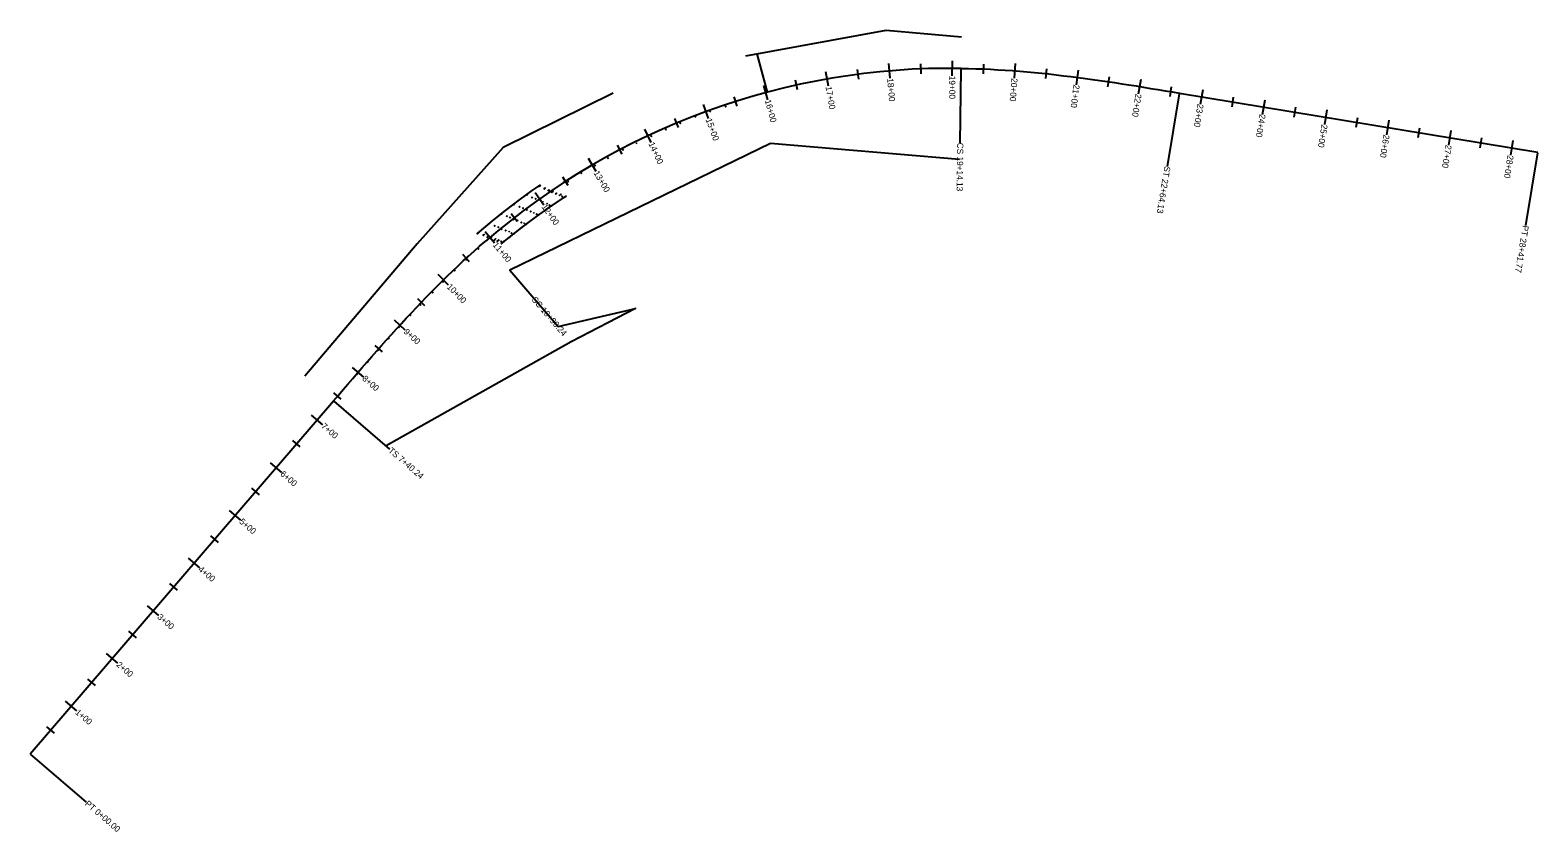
# Model space of a CAD drawing. Extents: x 153371 to 155769, y 329648 to 330923.
import ezdxf

# ---------------------------------------------------------------- set-up
doc = ezdxf.new("R2010")
doc.units = 0
for name, color, linetype in [('Default', 7, 'Continuous'), ('DT_X_Break_Line', 7, 'Continuous'), ('DT_X_Spot_Elev', 7, 'Continuous'), ('DT_X_Terrain_Ground_Line', 7, 'Continuous'), ('DT_X_Triangles', 7, 'Continuous'), ('DT_X_Void', 7, 'Continuous')]:
    doc.layers.add(name, color=color, linetype=linetype)

msp = doc.modelspace()

# ---------------------------------------------------------------- linework, layer by layer
at = {"layer": 'Default'}
for p, q in [((154526.9, 330885.3), (154543.2, 330824.1)), ((154640.7, 330833.5), (154636.6, 330856.7)), ((154640.7, 330833.5), (154636.6, 330856.7)), ((154689.1, 330844.8), (154687, 330860.4)), ((154689.1, 330844.8), (154687, 330860.4)), ((154738.8, 330846.2), (154736.8, 330869.7)), ((154738.8, 330846.2), (154736.8, 330869.7)), ((154788, 330853.2), (154787.3, 330869)), ((154788, 330853.2), (154787.3, 330869)), ((154837.6, 330850.2), (154837.7, 330873.9)), ((154837.6, 330850.2), (154837.7, 330873.9)), ((154850.3, 330743.8), (154851.8, 330860.9)), ((154850.3, 330743.8), (154851.8, 330860.9)), ((154887.3, 330853.2), (154887.9, 330868.9)), ((154887.3, 330853.2), (154887.9, 330868.9)), ((154936.6, 330846.3), (154938.4, 330869.9)), ((154936.6, 330846.3), (154938.4, 330869.9)), ((154986.5, 330845.7), (154988.2, 330861.4)), ((154986.5, 330845.7), (154988.2, 330861.4)), ((155035.4, 330835.9), (155038.5, 330859.3)), ((155035.4, 330835.9), (155038.5, 330859.3)), ((154544.1, 330812.1), (154538, 330834.9)), ((154544.1, 330812.1), (154538, 330834.9)), ((154591.3, 330827.7), (154587.9, 330843.1)), ((154591.3, 330827.7), (154587.9, 330843.1)), ((155085.3, 330832.9), (155087.7, 330848.5)), ((155085.3, 330832.9), (155087.7, 330848.5)), ((155134, 330821.4), (155137.8, 330844.7)), ((155134, 330821.4), (155137.8, 330844.7)), ((155184, 330817.2), (155186.5, 330832.7)), ((155184, 330817.2), (155186.5, 330832.7)), ((154495.4, 330802), (154490.6, 330817)), ((154495.4, 330802), (154490.6, 330817)), ((155179.9, 330706.1), (155199, 330821.7)), ((155179.9, 330706.1), (155199, 330821.7)), ((155232.7, 330805.2), (155236.5, 330828.5)), ((155232.7, 330805.2), (155236.5, 330828.5)), ((155282.6, 330800.9), (155285.2, 330816.5)), ((155282.6, 330800.9), (155285.2, 330816.5)), ((155331.3, 330788.9), (155335.2, 330812.2)), ((155331.3, 330788.9), (155335.2, 330812.2)), ((154402.2, 330767.9), (154396.1, 330782.4)), ((154402.2, 330767.9), (154396.1, 330782.4)), ((154449.8, 330782.3), (154441.6, 330804.5)), ((154449.8, 330782.3), (154441.6, 330804.5)), ((155381.3, 330784.6), (155383.9, 330800.2)), ((155381.3, 330784.6), (155383.9, 330800.2)), ((155430, 330772.6), (155433.8, 330795.9)), ((155430, 330772.6), (155433.8, 330795.9)), ((155480, 330768.4), (155482.5, 330783.9)), ((155480, 330768.4), (155482.5, 330783.9)), ((154358.4, 330744.2), (154348.4, 330765.6)), ((154358.4, 330744.2), (154348.4, 330765.6)), ((155528.7, 330756.4), (155532.5, 330779.7)), ((155528.7, 330756.4), (155532.5, 330779.7)), ((155578.6, 330752.1), (155581.2, 330767.6)), ((155578.6, 330752.1), (155581.2, 330767.6)), ((155627.3, 330740.1), (155631.2, 330763.4)), ((155627.3, 330740.1), (155631.2, 330763.4)), ((154312.3, 330725.7), (154305, 330739.7)), ((154312.3, 330725.7), (154305, 330739.7)), ((155677.3, 330735.8), (155679.9, 330751.4)), ((155677.3, 330735.8), (155679.9, 330751.4)), ((155726, 330723.8), (155729.8, 330747.1)), ((155726, 330723.8), (155729.8, 330747.1)), ((154270.8, 330698.3), (154259, 330718.7)), ((154270.8, 330698.3), (154259, 330718.7)), ((155749.9, 330612.1), (155769, 330727.7)), ((155749.9, 330612.1), (155769, 330727.7)), ((154226.5, 330675.7), (154218, 330689)), ((154226.5, 330675.7), (154218, 330689)), ((154187.6, 330644.8), (154174, 330664)), ((154187.6, 330644.8), (154174, 330664)), ((154145.5, 330618.4), (154135.8, 330630.8)), ((154145.5, 330618.4), (154135.8, 330630.8)), ((154109.5, 330584.1), (154094.2, 330602.1)), ((154109.5, 330584.1), (154094.2, 330602.1)), ((154069.6, 330554.3), (154059, 330565.9)), ((154069.6, 330554.3), (154059, 330565.9)), ((154036.3, 330517.3), (154019.7, 330534.1)), ((154036.3, 330517.3), (154019.7, 330534.1)), ((153998.5, 330484.7), (153987.2, 330495.6)), ((153998.5, 330484.7), (153987.2, 330495.6)), ((153967.4, 330445.7), (153950, 330461.6)), ((153967.4, 330445.7), (153950, 330461.6)), ((153931.1, 330411.3), (153919.3, 330421.7)), ((153931.1, 330411.3), (153919.3, 330421.7)), ((153901.2, 330371.1), (153883.4, 330386.6)), ((153901.2, 330371.1), (153883.4, 330386.6)), ((153865.6, 330335.9), (153853.7, 330346.1)), ((153865.6, 330335.9), (153853.7, 330346.1)), ((153942.9, 330256.6), (153854, 330333)), ((153942.9, 330256.6), (153854, 330333)), ((153836, 330295.4), (153818.1, 330310.8)), ((153836, 330295.4), (153818.1, 330310.8)), ((153800.4, 330260.1), (153788.5, 330270.3)), ((153800.4, 330260.1), (153788.5, 330270.3)), ((153770.8, 330219.6), (153752.9, 330235)), ((153770.8, 330219.6), (153752.9, 330235)), ((153735.2, 330184.2), (153723.3, 330194.5)), ((153735.2, 330184.2), (153723.3, 330194.5)), ((153705.6, 330143.8), (153687.7, 330159.2)), ((153705.6, 330143.8), (153687.7, 330159.2)), ((153670, 330108.4), (153658.1, 330118.7)), ((153670, 330108.4), (153658.1, 330118.7)), ((153640.4, 330067.9), (153622.5, 330083.4)), ((153640.4, 330067.9), (153622.5, 330083.4)), ((153604.8, 330032.6), (153592.8, 330042.9)), ((153604.8, 330032.6), (153592.8, 330042.9)), ((153575.2, 329992.1), (153557.3, 330007.5)), ((153575.2, 329992.1), (153557.3, 330007.5)), ((153539.6, 329956.8), (153527.6, 329967.1)), ((153539.6, 329956.8), (153527.6, 329967.1)), ((153510, 329916.3), (153492, 329931.7)), ((153510, 329916.3), (153492, 329931.7)), ((153474.4, 329881), (153462.4, 329891.2)), ((153474.4, 329881), (153462.4, 329891.2)), ((153444.8, 329840.5), (153426.8, 329855.9)), ((153444.8, 329840.5), (153426.8, 329855.9)), ((153409.2, 329805.2), (153397.2, 329815.4)), ((153409.2, 329805.2), (153397.2, 329815.4)), ((153460.1, 329695.4), (153371.3, 329771.7)), ((153460.1, 329695.4), (153371.3, 329771.7))]:
    msp.add_line(p, q, dxfattribs=at)
at = {"layer": 'DT_X_Break_Line'}
for points in [[(154509.3, 330882.2), (154732.2, 330922.7), (154852, 330911.9)], [(154297.9, 330822.6), (154123.1, 330736), (153986.5, 330583), (153807.8, 330372.7)], [(154849, 330716.9), (154548.6, 330742.6), (154133.5, 330541.2), (154210.4, 330451.7), (154333.4, 330480.2), (154231.3, 330427.4), (153936.7, 330261.9)]]:
    msp.add_lwpolyline(points, dxfattribs=at)
at = {"layer": 'DT_X_Spot_Elev'}
for points in [[(154181.4, 330676.3), (154168.9, 330667.6), (154148.8, 330653.1), (154126.4, 330635.9), (154108.2, 330621.5), (154081.9, 330599.7)], [(154120.5, 330583.7), (154132.7, 330593.2), (154153, 330609.1), (154171.9, 330623.5), (154194.5, 330639.6), (154222.3, 330658.5), (154222.7, 330659.1)]]:
    msp.add_lwpolyline(points, dxfattribs=at)
at = {"layer": 'DT_X_Terrain_Ground_Line'}
for p, q in [((154428.4, 330784.2), (154429.7, 330785.5)), ((154428.4, 330785.5), (154429.7, 330784.2)), ((154451.7, 330792.8), (154453.1, 330794.1)), ((154451.7, 330794.1), (154453.1, 330792.8)), ((154476.3, 330801.1), (154477.7, 330802.5)), ((154476.3, 330802.5), (154477.7, 330801.1)), ((154381.2, 330764.5), (154382.5, 330765.8)), ((154381.2, 330765.8), (154382.5, 330764.5)), ((154404.1, 330774.6), (154405.5, 330775.9)), ((154404.1, 330775.9), (154405.5, 330774.6)), ((154334.6, 330742.6), (154336, 330743.9)), ((154334.6, 330743.9), (154336, 330742.6)), ((154358.1, 330753.9), (154359.5, 330755.3)), ((154358.1, 330755.3), (154359.5, 330753.9)), ((154289.3, 330718.8), (154290.6, 330720.2)), ((154289.3, 330720.2), (154290.6, 330718.8)), ((154313, 330731.8), (154314.4, 330733.1)), ((154313, 330733.1), (154314.4, 330731.8)), ((154246.8, 330694.9), (154248.2, 330696.2)), ((154246.8, 330696.2), (154248.2, 330694.9)), ((154268.6, 330707.3), (154269.9, 330708.7)), ((154268.6, 330708.7), (154269.9, 330707.3)), ((154179.3, 330673.6), (154180.6, 330674.9)), ((154179.3, 330674.9), (154180.6, 330673.6)), ((154181, 330674.8), (154182.3, 330676.2)), ((154181, 330676.2), (154182.3, 330674.8)), ((154188, 330670), (154189.4, 330671.3)), ((154188, 330671.3), (154189.4, 330670)), ((154189, 330670.9), (154190.3, 330672.2)), ((154189, 330672.2), (154190.3, 330670.9)), ((154194.4, 330667.2), (154195.8, 330668.5)), ((154194.4, 330668.5), (154195.8, 330667.2)), ((154195.4, 330668), (154196.7, 330669.3)), ((154195.4, 330669.3), (154196.7, 330668)), ((154200, 330664.8), (154201.3, 330666.2)), ((154200, 330666.2), (154201.3, 330664.8)), ((154201.4, 330665.7), (154202.7, 330667.1)), ((154201.4, 330667.1), (154202.7, 330665.7)), ((154206.2, 330662.1), (154207.5, 330663.5)), ((154206.2, 330663.5), (154207.5, 330662.1)), ((154207.4, 330663), (154208.7, 330664.3)), ((154207.4, 330664.3), (154208.7, 330663)), ((154225.9, 330681.8), (154227.2, 330683.1)), ((154225.9, 330683.1), (154227.2, 330681.8)), ((154139.5, 330645.3), (154140.8, 330646.6)), ((154139.5, 330646.6), (154140.8, 330645.3)), ((154148.3, 330641.6), (154149.6, 330643)), ((154148.3, 330643), (154149.6, 330641.6)), ((154153.8, 330639), (154155.2, 330640.3)), ((154153.8, 330640.3), (154155.2, 330639)), ((154160.5, 330660.3), (154161.8, 330661.7)), ((154160.5, 330661.7), (154161.8, 330660.3)), ((154168.4, 330656.4), (154169.7, 330657.7)), ((154168.4, 330657.7), (154169.7, 330656.4)), ((154174.1, 330654.3), (154175.4, 330655.6)), ((154174.1, 330655.6), (154175.4, 330654.3)), ((154181.4, 330652.3), (154182.8, 330653.6)), ((154181.4, 330653.6), (154182.8, 330652.3)), ((154185.5, 330649.2), (154186.8, 330650.5)), ((154185.5, 330650.5), (154186.8, 330649.2)), ((154192.3, 330646.5), (154193.7, 330647.8)), ((154192.3, 330647.8), (154193.7, 330646.5)), ((154196.1, 330644.2), (154197.4, 330645.5)), ((154196.1, 330645.5), (154197.4, 330644.2)), ((154199.6, 330643.1), (154201, 330644.4)), ((154199.6, 330644.4), (154201, 330643.1)), ((154212.1, 330659.7), (154213.4, 330661.1)), ((154212.1, 330661.1), (154213.4, 330659.7)), ((154214.1, 330660.9), (154215.4, 330662.3)), ((154214.1, 330662.3), (154215.4, 330660.9)), ((154216.2, 330658), (154217.6, 330659.3)), ((154216.2, 330659.3), (154217.6, 330658)), ((154219, 330656.3), (154220.4, 330657.6)), ((154219, 330657.6), (154220.4, 330656.3)), ((154220.9, 330657.4), (154222.2, 330658.8)), ((154220.9, 330658.8), (154222.2, 330657.4)), ((154100.5, 330614.7), (154101.9, 330616)), ((154100.5, 330616), (154101.9, 330614.7)), ((154120, 330630.1), (154121.3, 330631.4)), ((154120, 330631.4), (154121.3, 330630.1)), ((154128.4, 330626.7), (154129.7, 330628)), ((154128.4, 330628), (154129.7, 330626.7)), ((154133.2, 330624.3), (154134.6, 330625.6)), ((154133.2, 330625.6), (154134.6, 330624.3)), ((154138.8, 330621.1), (154140.1, 330622.4)), ((154138.8, 330622.4), (154140.1, 330621.1)), ((154145.2, 330619.8), (154146.5, 330621.1)), ((154145.2, 330621.1), (154146.5, 330619.8)), ((154151.3, 330616.7), (154152.6, 330618.1)), ((154151.3, 330618.1), (154152.6, 330616.7)), ((154155.8, 330615.2), (154157.1, 330616.6)), ((154155.8, 330616.6), (154157.1, 330615.2)), ((154159.1, 330613.9), (154160.4, 330615.2)), ((154159.1, 330615.2), (154160.4, 330613.9)), ((154160.1, 330636.8), (154161.4, 330638.1)), ((154160.1, 330638.1), (154161.4, 330636.8)), ((154166.2, 330634.1), (154167.5, 330635.5)), ((154166.2, 330635.5), (154167.5, 330634.1)), ((154171.3, 330631.6), (154172.6, 330632.9)), ((154171.3, 330632.9), (154172.6, 330631.6)), ((154175.7, 330629.9), (154177, 330631.3)), ((154175.7, 330631.3), (154177, 330629.9)), ((154178.8, 330628.8), (154180.1, 330630.1)), ((154178.8, 330630.1), (154180.1, 330628.8)), ((154082.4, 330599.7), (154083.7, 330601)), ((154082.4, 330601), (154083.7, 330599.7)), ((154083.9, 330601), (154085.3, 330602.3)), ((154083.9, 330602.3), (154085.3, 330601)), ((154090.9, 330596.2), (154092.3, 330597.6)), ((154090.9, 330597.6), (154092.3, 330596.2)), ((154092.3, 330597.4), (154093.6, 330598.7)), ((154092.3, 330598.7), (154093.6, 330597.4)), ((154097.1, 330593.4), (154098.5, 330594.8)), ((154097.1, 330594.8), (154098.5, 330593.4)), ((154098.9, 330595.1), (154100.2, 330596.4)), ((154098.9, 330596.4), (154100.2, 330595.1)), ((154102.1, 330591.4), (154103.5, 330592.8)), ((154102.1, 330592.8), (154103.5, 330591.4)), ((154103.7, 330593), (154105.1, 330594.4)), ((154103.7, 330594.4), (154105.1, 330593)), ((154108.8, 330611.1), (154110.2, 330612.4)), ((154108.8, 330612.4), (154110.2, 330611.1)), ((154110.2, 330590.3), (154111.6, 330591.6)), ((154110.2, 330591.6), (154111.6, 330590.3)), ((154114.6, 330609), (154116, 330610.4)), ((154114.6, 330610.4), (154116, 330609)), ((154119.8, 330606.1), (154121.1, 330607.4)), ((154119.8, 330607.4), (154121.1, 330606.1)), ((154126.3, 330603.8), (154127.6, 330605.1)), ((154126.3, 330605.1), (154127.6, 330603.8)), ((154132, 330601.9), (154133.3, 330603.3)), ((154132, 330603.3), (154133.3, 330601.9)), ((154135.8, 330599.7), (154137.1, 330601)), ((154135.8, 330601), (154137.1, 330599.7)), ((154139.4, 330598.6), (154140.7, 330599.9)), ((154139.4, 330599.9), (154140.7, 330598.6)), ((154082.8, 330574.6), (154084.2, 330576)), ((154082.8, 330576), (154084.2, 330574.6)), ((154108.5, 330588.5), (154109.9, 330589.9)), ((154108.5, 330589.9), (154109.9, 330588.5)), ((154113.1, 330586.6), (154114.5, 330587.9)), ((154113.1, 330587.9), (154114.5, 330586.6)), ((154115.2, 330588.3), (154116.5, 330589.7)), ((154115.2, 330589.7), (154116.5, 330588.3)), ((154119.2, 330586.3), (154120.6, 330587.7)), ((154119.2, 330587.7), (154120.6, 330586.3)), ((154119.8, 330583.5), (154121.1, 330584.8)), ((154119.8, 330584.8), (154121.1, 330583.5)), ((154123.6, 330586.3), (154124.9, 330587.6)), ((154123.6, 330587.6), (154124.9, 330586.3)), ((154063.5, 330557), (154064.8, 330558.3)), ((154063.5, 330558.3), (154064.8, 330557)), ((154026.8, 330522), (154028.1, 330523.4)), ((154026.8, 330523.4), (154028.1, 330522)), ((154045.4, 330540.2), (154046.8, 330541.5)), ((154045.4, 330541.5), (154046.8, 330540.2)), ((154010.4, 330505.3), (154011.8, 330506.6)), ((154010.4, 330506.6), (154011.8, 330505.3)), ((153990.8, 330485.7), (153992.2, 330487)), ((153990.8, 330487), (153992.2, 330485.7)), ((153956.8, 330449.8), (153958.2, 330451.1)), ((153956.8, 330451.1), (153958.2, 330449.8)), ((153974.8, 330468.9), (153976.1, 330470.3)), ((153974.8, 330470.3), (153976.1, 330468.9)), ((153940.4, 330432.1), (153941.7, 330433.5)), ((153940.4, 330433.5), (153941.7, 330432.1)), ((153923.5, 330413.5), (153924.8, 330414.8)), ((153923.5, 330414.8), (153924.8, 330413.5)), ((153889.9, 330375.4), (153891.3, 330376.7)), ((153889.9, 330376.7), (153891.3, 330375.4)), ((153906.6, 330394.4), (153907.9, 330395.8)), ((153906.6, 330395.8), (153907.9, 330394.4))]:
    msp.add_line(p, q, dxfattribs=at)
at = {"layer": 'DT_X_Triangles'}
for p, q in [((154168.4, 330667.6), (154169.4, 330667.6)), ((154168.9, 330668.1), (154168.9, 330667.1)), ((154168.9, 330667.6), (154168.9, 330667.6)), ((154180.9, 330676.3), (154181.9, 330676.3)), ((154181.4, 330676.8), (154181.4, 330675.8)), ((154181.4, 330676.3), (154181.4, 330676.3)), ((154148.3, 330653.1), (154149.3, 330653.1)), ((154148.8, 330653.6), (154148.8, 330652.6)), ((154148.8, 330653.1), (154148.8, 330653.1)), ((154194, 330639.6), (154195, 330639.6)), ((154194.5, 330640.1), (154194.5, 330639.1)), ((154194.5, 330639.6), (154194.5, 330639.6)), ((154221.8, 330658.5), (154222.8, 330658.5)), ((154222.2, 330659.1), (154223.2, 330659.1)), ((154222.3, 330659), (154222.3, 330658)), ((154222.3, 330658.5), (154222.3, 330658.5)), ((154222.7, 330659.6), (154222.7, 330658.6)), ((154222.7, 330659.1), (154222.7, 330659.1)), ((154107.7, 330621.5), (154108.7, 330621.5)), ((154108.2, 330622), (154108.2, 330621)), ((154108.2, 330621.5), (154108.2, 330621.5)), ((154125.9, 330635.9), (154126.9, 330635.9)), ((154126.4, 330636.4), (154126.4, 330635.4)), ((154126.4, 330635.9), (154126.4, 330635.9)), ((154171.4, 330623.5), (154172.4, 330623.5)), ((154171.9, 330624), (154171.9, 330623)), ((154171.9, 330623.5), (154171.9, 330623.5)), ((154081.4, 330599.7), (154082.4, 330599.7)), ((154081.9, 330600.2), (154081.9, 330599.2)), ((154081.9, 330599.7), (154081.9, 330599.7)), ((154132.2, 330593.2), (154133.2, 330593.2)), ((154132.7, 330593.7), (154132.7, 330592.7)), ((154132.7, 330593.2), (154132.7, 330593.2)), ((154152.5, 330609.1), (154153.5, 330609.1)), ((154153, 330609.6), (154153, 330608.6)), ((154153, 330609.1), (154153, 330609.1)), ((154120, 330583.7), (154121, 330583.7)), ((154120.5, 330584.2), (154120.5, 330583.2)), ((154120.5, 330583.7), (154120.5, 330583.7))]:
    msp.add_line(p, q, dxfattribs=at)
at = {"layer": 'DT_X_Void'}
for points in [[(154851.8, 330861.9), (154863.4, 330861.7), (154875.1, 330861.5), (154886.8, 330861.1), (154898.4, 330860.6), (154910.1, 330859.9), (154921.7, 330859.2), (154933.3, 330858.4), (154945, 330857.5), (154956.6, 330856.6), (154968.2, 330855.5), (154979.8, 330854.3), (154991.4, 330853.1), (155003, 330851.8), (155014.6, 330850.4), (155026.2, 330849), (155037.8, 330847.5), (155049.3, 330846), (155060.9, 330844.4), (155072.4, 330842.7), (155084, 330841.1), (155095.5, 330839.3), (155107.1, 330837.6), (155118.6, 330835.8), (155130.1, 330834), (155141.6, 330832.1), (155153.1, 330830.2), (155164.7, 330828.4), (155176.2, 330826.5), (155187.7, 330824.6), (155199.2, 330822.7), (155769.1, 330728.7)], [(153370.6, 329772.4), (153853.3, 330333.6), (153860.9, 330342.5), (153868.5, 330351.3), (153876.1, 330360.1), (153883.7, 330369), (153891.3, 330377.8), (153899, 330386.6), (153906.7, 330395.4), (153914.3, 330404.2), (153922.1, 330412.9), (153929.8, 330421.7), (153937.6, 330430.4), (153945.4, 330439.1), (153953.2, 330447.7), (153961.1, 330456.3), (153969, 330464.9), (153977, 330473.4), (153985, 330481.9), (153993, 330490.3), (154001.1, 330498.7), (154009.3, 330507), (154017.5, 330515.3), (154025.8, 330523.5), (154034.1, 330531.7), (154042.5, 330539.8), (154051, 330547.8), (154059.6, 330555.8), (154068.2, 330563.6), (154076.9, 330571.4), (154085.6, 330579.1), (154094.5, 330586.7)]]:
    msp.add_lwpolyline(points, dxfattribs=at)
msp.add_arc((154833.7, 329732.1), 1130, 89.0816, 130.8562, dxfattribs=at)

# ---------------------------------------------------------------- texts
at = {"layer": 'Default'}
for s, height, rotation, p in [('17+00', 9.84, 279.9388, (154635.8, 330832.6)), ('17+00', 9.84, 279.9388, (154635.8, 330832.6)), ('18+00', 9.84, 274.8684, (154733.9, 330845.8)), ('18+00', 9.84, 274.8684, (154733.9, 330845.8)), ('19+00', 9.84, 269.798, (154832.7, 330850.3)), ('19+00', 9.84, 269.798, (154832.7, 330850.3)), ('20+00', 9.84, 265.6504, (154931.7, 330846.7)), ('20+00', 9.84, 265.6504, (154931.7, 330846.7)), ('21+00', 9.84, 262.5483, (155030.6, 330836.6)), ('21+00', 9.84, 262.5483, (155030.6, 330836.6)), ('16+00', 9.84, 285.0092, (154539.3, 330810.8)), ('16+00', 9.84, 285.0092, (154539.3, 330810.8)), ('22+00', 9.84, 260.8949, (155129.2, 330822.1)), ('22+00', 9.84, 260.8949, (155129.2, 330822.1)), ('23+00', 9.84, 260.6356, (155227.8, 330806)), ('23+00', 9.84, 260.6356, (155227.8, 330806)), ('24+00', 9.84, 260.6356, (155326.5, 330789.7)), ('24+00', 9.84, 260.6356, (155326.5, 330789.7)), ('15+00', 9.84, 290.0797, (154445.1, 330780.6)), ('15+00', 9.84, 290.0797, (154445.1, 330780.6)), ('25+00', 9.84, 260.6356, (155425.1, 330773.4)), ('25+00', 9.84, 260.6356, (155425.1, 330773.4)), ('14+00', 9.84, 295.1501, (154354, 330742.1)), ('14+00', 9.84, 295.1501, (154354, 330742.1)), ('CS 19+14.13', 9.842, 269.2759, (154845.4, 330743.9)), ('CS 19+14.13', 9.843, 269.2759, (154845.4, 330743.9)), ('26+00', 9.84, 260.6356, (155523.8, 330757.2)), ('26+00', 9.84, 260.6356, (155523.8, 330757.2)), ('27+00', 9.84, 260.6356, (155622.5, 330740.9)), ('27+00', 9.84, 260.6356, (155622.5, 330740.9)), ('28+00', 9.84, 260.6356, (155721.1, 330724.6)), ('28+00', 9.84, 260.6356, (155721.1, 330724.6)), ('13+00', 9.84, 300.2205, (154266.6, 330695.8)), ('13+00', 9.84, 300.2205, (154266.6, 330695.8)), ('ST 22+64.13', 9.842, 260.6163, (155175.1, 330706.9)), ('ST 22+64.13', 9.842, 260.6163, (155175.1, 330706.9)), ('12+00', 9.84, 305.2909, (154183.6, 330641.9)), ('12+00', 9.84, 305.2909, (154183.6, 330641.9)), ('PT 28+41.77', 9.843, 260.6356, (155745.1, 330612.9)), ('PT 28+41.77', 9.842, 260.6356, (155745.1, 330612.9)), ('11+00', 9.84, 310.3613, (154105.8, 330580.9)), ('11+00', 9.84, 310.3613, (154105.8, 330580.9)), ('10+00', 9.84, 314.455, (154032.8, 330513.8)), ('10+00', 9.84, 314.455, (154032.8, 330513.8)), ('SC 10+90.24', 9.843, 310.6627, (154167.7, 330493.9)), ('SC 10+90.24', 9.842, 310.6627, (154167.7, 330493.9)), ('9+00', 9.84, 317.4937, (153964, 330442.1)), ('9+00', 9.84, 317.4937, (153964, 330442.1)), ('8+00', 9.84, 319.0838, (153898, 330367.4)), ('8+00', 9.84, 319.0838, (153898, 330367.4)), ('7+00', 9.84, 319.3022, (153832.8, 330291.7)), ('7+00', 9.84, 319.3022, (153832.8, 330291.7)), ('TS 7+40.24', 9.84, 319.3224, (153939.6, 330252.9)), ('TS 7+40.24', 9.84, 319.3224, (153939.6, 330252.9)), ('6+00', 9.84, 319.3022, (153767.6, 330215.8)), ('6+00', 9.84, 319.3022, (153767.6, 330215.8)), ('5+00', 9.84, 319.3022, (153702.4, 330140)), ('5+00', 9.84, 319.3022, (153702.4, 330140)), ('4+00', 9.84, 319.3022, (153637.2, 330064.2)), ('4+00', 9.84, 319.3022, (153637.2, 330064.2)), ('3+00', 9.84, 319.3022, (153572, 329988.4)), ('3+00', 9.84, 319.3022, (153572, 329988.4)), ('2+00', 9.84, 319.3022, (153506.8, 329912.6)), ('2+00', 9.84, 319.3022, (153506.8, 329912.6)), ('1+00', 9.84, 319.3022, (153441.5, 329836.8)), ('1+00', 9.84, 319.3022, (153441.5, 329836.8)), ('PT 0+00.00', 9.84, 319.3022, (153456.9, 329691.6)), ('PT 0+00.00', 9.84, 319.3022, (153456.9, 329691.6))]:
    msp.add_text(s, height=height, rotation=rotation, dxfattribs=at).set_placement(p)

doc.saveas('drawing.dxf')
